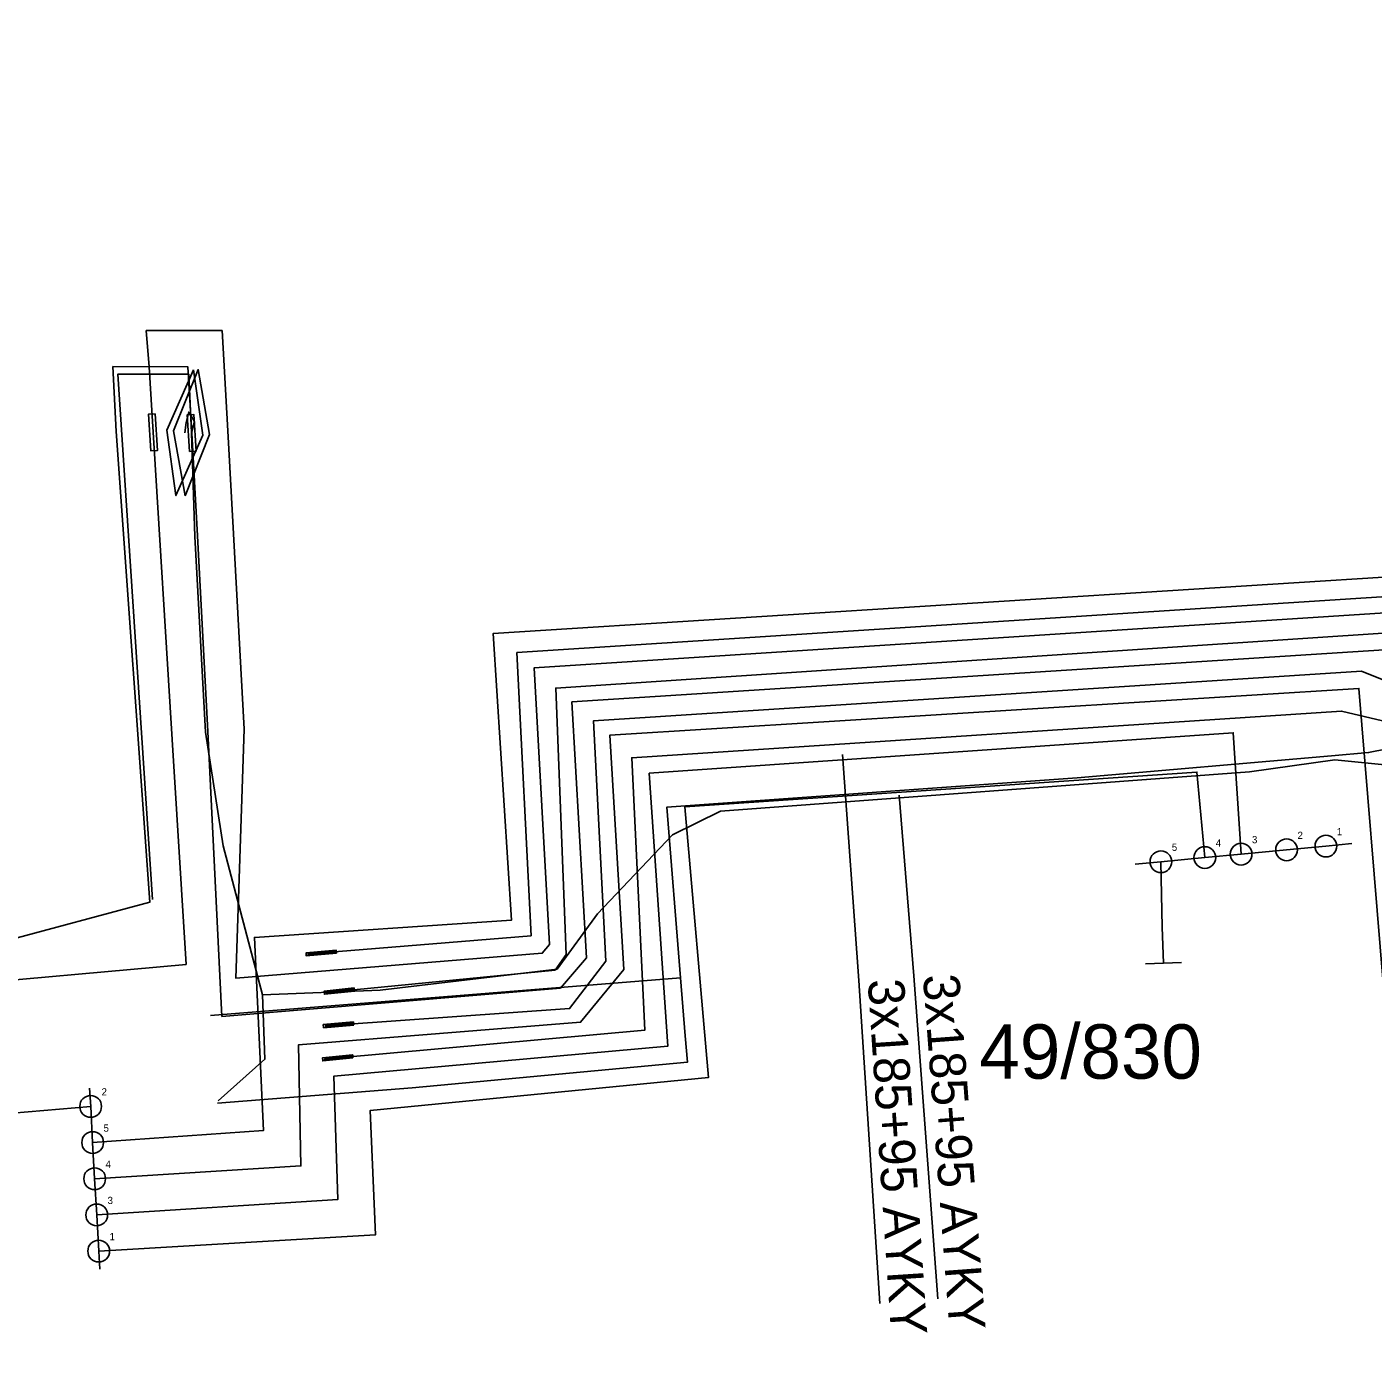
# Model space of a CAD drawing. Extents: x -744800 to -744528, y -1052473 to -1052336.
# Drawn here: x -744703.68 to -744666.55, y -1052374.67 to -1052338.05 of the extents above; entities that cross this region are included whole.
import ezdxf

# ---------------------------------------------------------------- set-up
doc = ezdxf.new("R2010")
doc.units = 0
for name, color, linetype in [('NN_CISLO_VYVODU', 7, 'Continuous'), ('NN_KABEL_INSTALACE_RIS_PROVOZ', 7, 'Continuous'), ('NN_KABELOVE_VEDENI_PROVOZ', 7, 'Continuous'), ('NN_KABELOVE_VEDENI_VYRAZENO', 7, 'Continuous'), ('NN_POPIS_USEKU', 7, 'Continuous'), ('NN_PRIPOJNICE_RIS', 7, 'Continuous'), ('NN_PRIPOJOVACI_MISTO', 7, 'Continuous'), ('NN_RIS', 7, 'Continuous'), ('NN_SPOJKA', 7, 'Continuous'), ('NN_VYVODY', 7, 'Continuous'), ('TR_SPOJKOVISTE_NN', 7, 'Continuous'), ('TRASA_KABELU_NN', 7, 'Continuous'), ('TRASA_KABELU_NN_PROVOZ', 7, 'Continuous')]:
    doc.layers.add(name, color=color, linetype=linetype)

msp = doc.modelspace()

# ---------------------------------------------------------------- linework, layer by layer
at = {"layer": 'NN_KABEL_INSTALACE_RIS_PROVOZ'}
for p, q in [((-744672.369, -1052362.895), (-744672.405, -1052361.088)), ((-744706.698, -1052368.247), (-744701.925, -1052367.838))]:
    msp.add_line(p, q, dxfattribs=at)
at = {"layer": 'NN_KABELOVE_VEDENI_PROVOZ'}
for points in [[(-744624.583, -1052390.597), (-744662.551, -1052395.016), (-744662.948, -1052380.543), (-744665.084, -1052354.146), (-744689.69, -1052355.734), (-744689.271, -1052363.374), (-744689.47, -1052363.612), (-744697.923, -1052364.3), (-744697.691, -1052357.426), (-744697.981, -1052352.043), (-744698.141, -1052349.202), (-744698.301, -1052346.432), (-744700.392, -1052346.432), (-744700.314, -1052347.432), (-744700.205, -1052349.239)], [(-744699.139, -1052349.258), (-744699.243, -1052347.432), (-744701.311, -1052347.427), (-744701.218, -1052349.218), (-744700.291, -1052362.199), (-744704.327, -1052363.291), (-744737.386, -1052365.889), (-744740.604, -1052362.488), (-744742.06, -1052359.669), (-744743.417, -1052358.06), (-744745.19, -1052357.685), (-744754.658, -1052357.57), (-744756.199, -1052357.576)], [(-744700.205, -1052349.239), (-744699.678, -1052357.717), (-744699.293, -1052363.92), (-744737.592, -1052367.36), (-744741.627, -1052363.126), (-744743.413, -1052360.15), (-744744.273, -1052359.091), (-744745.662, -1052358.694), (-744756.217, -1052358.577)], [(-744625.43, -1052391.735), (-744663.451, -1052396.18), (-744663.9, -1052380.649), (-744665.964, -1052355.222), (-744688.65, -1052356.68), (-744688.253, -1052363.744), (-744688.967, -1052364.578), (-744698.307, -1052365.358), (-744698.689, -1052357.494), (-744698.979, -1052352.097), (-744699.139, -1052349.258)], [(-744632.192, -1052356.508), (-744632.59, -1052352.533), (-744627.595, -1052352.131), (-744624.97, -1052387.437), (-744628.541, -1052390.068), (-744661.572, -1052393.905), (-744661.969, -1052380.543), (-744664.088, -1052353.097), (-744690.819, -1052354.788), (-744690.316, -1052362.699), (-744697.407, -1052363.175), (-744697.161, -1052368.506), (-744701.87, -1052368.837)], [(-744626.303, -1052392.793), (-744664.403, -1052397.238), (-744664.932, -1052380.702), (-744666.943, -1052356.307), (-744687.604, -1052357.593), (-744687.221, -1052364.062), (-744688.411, -1052365.517), (-744696.19, -1052366.139), (-744696.124, -1052369.48), (-744701.815, -1052369.835)], [(-744701.759, -1052370.834), (-744695.108, -1052370.411), (-744695.214, -1052367.004), (-744686.006, -1052366.178), (-744686.52, -1052358.648), (-744670.408, -1052357.527), (-744670.194, -1052360.878)], [(-744701.704, -1052371.832), (-744694.071, -1052371.385), (-744694.219, -1052367.956), (-744684.884, -1052367.046), (-744685.534, -1052359.569), (-744671.413, -1052358.612), (-744671.194, -1052360.973)]]:
    msp.add_lwpolyline(points, dxfattribs=at)
at = {"layer": 'NN_KABELOVE_VEDENI_VYRAZENO'}
for points in [[(-744633.56, -1052338.275), (-744632.802, -1052350.057), (-744635.109, -1052350.226), (-744635.003, -1052352.11), (-744644.8, -1052352.796), (-744662.199, -1052356.204), (-744664.887, -1052353.685), (-744690.17, -1052355.317), (-744689.776, -1052363.13), (-744695.539, -1052363.606)], [(-744535.795, -1052343.306), (-744536.843, -1052338.052), (-744584.484, -1052351.418), (-744625.541, -1052352.533), (-744625.774, -1052350.057), (-744634.558, -1052350.692), (-744634.453, -1052352.618), (-744644.706, -1052353.278), (-744662.54, -1052356.847), (-744665.582, -1052354.733), (-744689.095, -1052356.294), (-744688.812, -1052363.65), (-744689.117, -1052364.084), (-744695.043, -1052364.655)], [(-744695.064, -1052365.586), (-744688.714, -1052365.142), (-744687.72, -1052363.83), (-744688.058, -1052357.204), (-744666.87, -1052355.829), (-744663.039, -1052357.374), (-744644.539, -1052353.754), (-744633.944, -1052353.041), (-744634.05, -1052351.136), (-744626.176, -1052350.586), (-744625.986, -1052353.084), (-744584.452, -1052351.895), (-744537.287, -1052338.607), (-744536.224, -1052343.513)], [(-744635.205, -1052353.712), (-744644.666, -1052354.305), (-744663.06, -1052357.966), (-744667.421, -1052356.929), (-744687, -1052358.22), (-744686.64, -1052365.735), (-744695.085, -1052366.497)]]:
    msp.add_lwpolyline(points, dxfattribs=at)
at = {"layer": 'NN_POPIS_USEKU'}
for points in [[(-744681.186, -1052358.127), (-744680.742, -1052364.364), (-744680.156, -1052373.281)], [(-744679.627, -1052359.253), (-744679.22, -1052364.239), (-744678.555, -1052373.15)]]:
    msp.add_lwpolyline(points, dxfattribs=at)
at = {"layer": 'NN_PRIPOJNICE_RIS'}
for points in [[(-744673.115, -1052361.155), (-744672.405, -1052361.088), (-744671.194, -1052360.973), (-744670.194, -1052360.878), (-744668.938, -1052360.759), (-744667.854, -1052360.657), (-744667.141, -1052360.589)], [(-744701.953, -1052367.339), (-744701.925, -1052367.838), (-744701.87, -1052368.837), (-744701.815, -1052369.835), (-744701.759, -1052370.834), (-744701.704, -1052371.832), (-744701.676, -1052372.331)]]:
    msp.add_lwpolyline(points, dxfattribs=at)
at = {"layer": 'NN_PRIPOJOVACI_MISTO'}
for p, q in [((-744672.334, -1052363.884), (-744672.369, -1052362.895)), ((-744671.84, -1052363.867), (-744672.829, -1052363.902))]:
    msp.add_line(p, q, dxfattribs=at)
at = {"layer": 'NN_SPOJKA'}
for points in [[(-744700.149, -1052348.728), (-744700.078, -1052349.737), (-744700.261, -1052349.75), (-744700.332, -1052348.741)], [(-744699.195, -1052349.769), (-744699.266, -1052348.76), (-744699.083, -1052348.747), (-744699.012, -1052349.756)], [(-744695.145, -1052363.614), (-744695.978, -1052363.687), (-744695.985, -1052363.603), (-744695.152, -1052363.53), (-744695.15, -1052363.558), (-744695.927, -1052363.626), (-744695.924, -1052363.654), (-744695.147, -1052363.586)], [(-744694.649, -1052364.656), (-744695.48, -1052364.743), (-744695.489, -1052364.66), (-744694.658, -1052364.572), (-744694.655, -1052364.6), (-744695.43, -1052364.682), (-744695.427, -1052364.709), (-744694.652, -1052364.628)], [(-744694.67, -1052365.594), (-744695.503, -1052365.667), (-744695.51, -1052365.583), (-744694.677, -1052365.51), (-744694.675, -1052365.538), (-744695.452, -1052365.606), (-744695.449, -1052365.634), (-744694.672, -1052365.566)], [(-744694.691, -1052366.498), (-744695.522, -1052366.585), (-744695.531, -1052366.502), (-744694.7, -1052366.414), (-744694.697, -1052366.442), (-744695.472, -1052366.524), (-744695.469, -1052366.551), (-744694.694, -1052366.47)]]:
    msp.add_lwpolyline(points, close=True, dxfattribs=at)
at = {"layer": 'NN_VYVODY'}
for centre in [(-744671.194, -1052360.973), (-744670.194, -1052360.878), (-744668.938, -1052360.759), (-744667.854, -1052360.657), (-744672.405, -1052361.088), (-744701.925, -1052367.838), (-744701.87, -1052368.837), (-744701.815, -1052369.835), (-744701.759, -1052370.834), (-744701.704, -1052371.832)]:
    msp.add_circle(centre, 0.3, dxfattribs=at)
at = {"layer": 'TR_SPOJKOVISTE_NN'}
for points in [[(-744699.088, -1052347.517), (-744698.835, -1052349.318), (-744699.572, -1052350.983), (-744699.825, -1052349.18), (-744699.088, -1052347.517)], [(-744699.321, -1052350.991), (-744699.637, -1052349.2), (-744698.959, -1052347.509), (-744698.643, -1052349.302), (-744699.321, -1052350.991)]]:
    msp.add_lwpolyline(points, dxfattribs=at)
at = {"layer": 'TRASA_KABELU_NN'}
msp.add_line((-744685.653, -1052364.292), (-744698.619, -1052365.334), dxfattribs=at)
msp.add_lwpolyline([(-744667.699, -1052358.163), (-744666.677, -1052358.075), (-744664.755, -1052357.699), (-744644.667, -1052353.764), (-744632.196, -1052352.864)], dxfattribs=at)
at = {"layer": 'TRASA_KABELU_NN_PROVOZ'}
for points in [[(-744700.223, -1052362.131), (-744701.175, -1052347.631), (-744699.218, -1052347.631), (-744699.14, -1052349.25)], [(-744699.14, -1052349.25), (-744699.06, -1052348.94), (-744699.22, -1052348.68), (-744699.29, -1052348.97), (-744699.33, -1052349.25)], [(-744697.19, -1052364.76), (-744698.27, -1052360.65), (-744698.76, -1052357.51), (-744699.05, -1052352.11), (-744699.14, -1052349.25)], [(-744753.927, -1052358.92), (-744752.388, -1052357.631), (-744748.988, -1052357.664), (-744745.19, -1052357.685), (-744743.417, -1052358.06), (-744742.06, -1052359.669), (-744740.604, -1052362.488), (-744737.386, -1052365.889), (-744730.179, -1052365.269), (-744720.866, -1052364.599), (-744712.961, -1052363.84), (-744705.806, -1052363.36), (-744704.327, -1052363.291), (-744700.291, -1052362.199)], [(-744626.65, -1052390.5), (-744629.4, -1052390.98), (-744636.83, -1052391.53), (-744649.33, -1052393.07), (-744662.48, -1052394.46), (-744663.54, -1052393.95), (-744663.69, -1052389.23), (-744663.86, -1052383.07), (-744664, -1052379.52), (-744664.68, -1052371.75), (-744665.64, -1052359.18), (-744666.23, -1052358.41), (-744667.61, -1052358.28), (-744669.96, -1052358.61), (-744684.55, -1052359.69), (-744685.88, -1052360.35), (-744687.95, -1052362.53), (-744689.06, -1052364.05), (-744693.94, -1052364.63), (-744697.19, -1052364.76)], [(-744685.653, -1052364.292), (-744686.031, -1052359.578), (-744674.718, -1052358.769), (-744667.699, -1052358.163)], [(-744698.43, -1052367.754), (-744693.058, -1052367.326), (-744685.461, -1052366.614), (-744685.525, -1052365.89), (-744685.653, -1052364.292)], [(-744697.19, -1052364.76), (-744697.12, -1052366.54), (-744698.41, -1052367.69)]]:
    msp.add_lwpolyline(points, dxfattribs=at)

# ---------------------------------------------------------------- texts
at = {"layer": 'NN_CISLO_VYVODU'}
for s, p in [('2', (-744668.638, -1052360.459)), ('1', (-744667.554, -1052360.357)), ('5', (-744672.105, -1052360.788)), ('4', (-744670.894, -1052360.673)), ('3', (-744669.894, -1052360.578)), ('2', (-744701.625, -1052367.538)), ('5', (-744701.57, -1052368.537)), ('4', (-744701.515, -1052369.535)), ('3', (-744701.459, -1052370.534)), ('1', (-744701.404, -1052371.532))]:
    msp.add_text(s, height=0.2, dxfattribs=at).set_placement(p)
at = {"layer": 'NN_POPIS_USEKU'}
for rotation, p in [(273.76, (-744680.492, -1052364.347)), (274.2706, (-744678.971, -1052364.221))]:
    msp.add_text('3x185+95 AYKY', height=1, rotation=rotation, dxfattribs=at).set_placement(p)
at = {"layer": 'NN_RIS'}
msp.add_text('49/830', height=1.5, dxfattribs=at).set_placement((-744677.411, -1052367.075))

doc.saveas('drawing.dxf')
